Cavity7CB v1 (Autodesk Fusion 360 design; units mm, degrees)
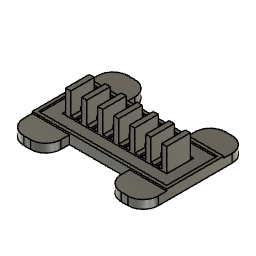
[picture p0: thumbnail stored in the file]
sketch "Sketch1" plane through (0, 0, 0) normal (0, 0, 1) x axis (1, 0, 0)
  line L1 (3, 0) -> (0, 0)
  line L2 (3, 14) -> (3, 0)
  line L3 (0, 14) -> (3, 14)
  line L4 (0, 0) -> (0, 14)
  line L5 (9.5, 14) -> (3, 14)
  line L6 (9.5, 0) -> (9.5, 14)
  line L7 (3, 0) -> (9.5, 0)
  line L8 (9.5, 8) -> (3, 8)
  line L9 (9.5, 6) -> (3, 6)
  line L10 (7, 5.5) -> (5.5, 5.5)
  line L11 (7, 0.7) -> (7, 5.5)
  line L12 (5.5, 0.7) -> (7, 0.7)
  line L13 (5.5, 5.5) -> (5.5, 0.7)
  line L14 (12.5, 0) -> (9.5, 0)
  line L15 (12.5, 14) -> (12.5, 0)
  line L16 (9.5, 14) -> (12.5, 14)
  line L17 (9.5, 0) -> (9.5, 14)
  line L18 (19, 14) -> (12.5, 14)
  line L19 (19, 0) -> (19, 14)
  line L20 (12.5, 0) -> (19, 0)
  line L21 (19, 8) -> (12.5, 8)
  line L22 (19, 6) -> (12.5, 6)
  line L23 (19, 6) -> (19, 8)
  line L24 (12.5, 6) -> (12.5, 8)
  line L25 (16.5, 5.5) -> (15, 5.5)
  line L26 (16.5, 0.7) -> (16.5, 5.5)
  line L27 (15, 0.7) -> (16.5, 0.7)
  line L28 (15, 5.5) -> (15, 0.7)
  line L29 (22, 14) -> (19, 14)
  line L30 (22, 0) -> (22, 14)
  line L31 (19, 0) -> (22, 0)
  line L32 (19, 14) -> (19, 0)
  line L33 (28.5, 14) -> (22, 14)
  line L34 (28.5, 0) -> (28.5, 14)
  line L35 (22, 0) -> (28.5, 0)
  line L36 (22, 14) -> (22, 0)
  line L37 (28.5, 8) -> (22, 8)
  line L38 (28.5, 6) -> (28.5, 8)
  line L39 (22, 6) -> (28.5, 6)
  line L40 (22, 8) -> (22, 6)
  line L41 (26, 5.5) -> (24.5, 5.5)
  line L42 (26, 0.7) -> (26, 5.5)
  line L43 (24.5, 0.7) -> (26, 0.7)
  line L44 (24.5, 5.5) -> (24.5, 0.7)
  line L45 (31.5, 14) -> (28.5, 14)
  line L46 (31.5, 0) -> (31.5, 14)
  line L47 (28.5, 0) -> (31.5, 0)
  line L48 (28.5, 14) -> (28.5, 0)
  line L49 (38, 14) -> (31.5, 14)
  line L50 (38, 0) -> (38, 14)
  line L51 (31.5, 0) -> (38, 0)
  line L52 (31.5, 14) -> (31.5, 0)
  line L53 (41, 14) -> (38, 14)
  line L54 (41, 0) -> (41, 14)
  line L55 (38, 0) -> (41, 0)
  line L56 (38, 14) -> (38, 0)
  line L57 (47.5, 14) -> (41, 14)
  line L58 (47.5, 0) -> (47.5, 14)
  line L59 (41, 0) -> (47.5, 0)
  line L60 (41, 14) -> (41, 0)
  line L61 (50.5, 14) -> (47.5, 14)
  line L62 (50.5, 0) -> (50.5, 14)
  line L63 (47.5, 0) -> (50.5, 0)
  line L64 (47.5, 14) -> (47.5, 0)
  line L65 (57, 14) -> (50.5, 14)
  line L66 (57, 0) -> (57, 14)
  line L67 (50.5, 0) -> (57, 0)
  line L68 (50.5, 14) -> (50.5, 0)
  line L69 (60, 14) -> (57, 14)
  line L70 (60, 0) -> (60, 14)
  line L71 (57, 0) -> (60, 0)
  line L72 (57, 14) -> (57, 0)
  line L73 (38, 8) -> (31.5, 8)
  line L74 (38, 6) -> (38, 8)
  line L75 (31.5, 6) -> (38, 6)
  line L76 (31.5, 8) -> (31.5, 6)
  line L77 (47.5, 8) -> (41, 8)
  line L78 (47.5, 6) -> (47.5, 8)
  line L79 (41, 6) -> (47.5, 6)
  line L80 (41, 8) -> (41, 6)
  line L81 (57, 8) -> (50.5, 8)
  line L82 (57, 6) -> (57, 8)
  line L83 (50.5, 6) -> (57, 6)
  line L84 (50.5, 8) -> (50.5, 6)
  line L85 (35.5, 5.5) -> (34, 5.5)
  line L86 (35.5, 0.7) -> (35.5, 5.5)
  line L87 (34, 0.7) -> (35.5, 0.7)
  line L88 (34, 5.5) -> (34, 0.7)
  line L89 (45, 5.5) -> (43.5, 5.5)
  line L90 (45, 0.7) -> (45, 5.5)
  line L91 (43.5, 0.7) -> (45, 0.7)
  line L92 (43.5, 5.5) -> (43.5, 0.7)
  line L93 (54.5, 5.5) -> (53, 5.5)
  line L94 (54.5, 0.7) -> (54.5, 5.5)
  line L95 (53, 0.7) -> (54.5, 0.7)
  line L96 (53, 5.5) -> (53, 0.7)
  line L97 (62, 7) -> (-6, 7)
  line L98 (54.5, 8.5) -> (53, 8.5)
  line L99 (53, 8.5) -> (53, 13.3)
  line L100 (53, 13.3) -> (54.5, 13.3)
  line L101 (54.5, 13.3) -> (54.5, 8.5)
  line L102 (43.5, 13.3) -> (45, 13.3)
  line L103 (45, 13.3) -> (45, 8.5)
  line L104 (45, 8.5) -> (43.5, 8.5)
  line L105 (43.5, 8.5) -> (43.5, 13.3)
  line L106 (35.5, 8.5) -> (34, 8.5)
  line L107 (34, 8.5) -> (34, 13.3)
  line L108 (34, 13.3) -> (35.5, 13.3)
  line L109 (35.5, 13.3) -> (35.5, 8.5)
  line L110 (24.5, 13.3) -> (26, 13.3)
  line L111 (24.5, 8.5) -> (24.5, 13.3)
  line L112 (26, 8.5) -> (24.5, 8.5)
  line L113 (26, 13.3) -> (26, 8.5)
  line L114 (16.5, 13.3) -> (16.5, 8.5)
  line L115 (15, 13.3) -> (16.5, 13.3)
  line L116 (15, 8.5) -> (15, 13.3)
  line L117 (16.5, 8.5) -> (15, 8.5)
  line L118 (7, 13.3) -> (7, 8.5)
  line L119 (5.5, 13.3) -> (7, 13.3)
  line L120 (5.5, 8.5) -> (5.5, 13.3)
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  point P1 (0, 0)
  point P2 (0, 0)
  point P8 (3, 8)
  point P9 (9.5, 8)
  point P10 (3, 6)
  point P11 (9.5, 6)
  point P21 (12.5, 8)
  point P22 (19, 8)
  point P23 (12.5, 6)
  point P24 (19, 6)
  point P35 (22, 8)
  point P64 (31.5, 8)
  point P68 (41, 8)
  point P72 (50.5, 8)
  point P12 (5.5, 5.5)
  point P113 (5.5, 8.5)
  point P13 (7, 5.5)
  point P110 (7, 8.5)
  point P14 (7, 0.7)
  point P111 (7, 13.3)
  point P15 (5.5, 0.7)
  point P112 (5.5, 13.3)
  point P25 (15, 5.5)
  point P109 (15, 8.5)
  point P26 (16.5, 5.5)
  point P106 (16.5, 8.5)
  point P27 (16.5, 0.7)
  point P107 (16.5, 13.3)
  point P28 (15, 0.7)
  point P108 (15, 13.3)
  point P39 (24.5, 5.5)
  point P104 (24.5, 8.5)
  point P40 (26, 5.5)
  point P105 (26, 8.5)
  point P41 (26, 0.7)
  point P102 (26, 13.3)
  point P42 (24.5, 0.7)
  point P103 (24.5, 13.3)
  point P76 (34, 5.5)
  point P98 (34, 8.5)
  point P77 (35.5, 5.5)
  point P99 (35.5, 8.5)
  point P78 (35.5, 0.7)
  point P101 (35.5, 13.3)
  point P79 (34, 0.7)
  point P100 (34, 13.3)
  point P80 (43.5, 5.5)
  point P97 (43.5, 8.5)
  point P81 (45, 5.5)
  point P96 (45, 8.5)
  point P82 (45, 0.7)
  point P94 (45, 13.3)
  point P83 (43.5, 0.7)
  point P95 (43.5, 13.3)
  point P84 (53, 5.5)
  point P90 (53, 8.5)
  point P85 (54.5, 5.5)
  point P91 (54.5, 8.5)
  point P86 (54.5, 0.7)
  point P93 (54.5, 13.3)
  point P87 (53, 0.7)
  point P92 (53, 13.3)
  point P114 (0, 0)
  point P3 (3, 0)
  point P5 (0, 14)
  point P4 (3, 14)
  point P6 (9.5, 14)
  point P7 (9.5, 0)
  point P16 (12.5, 0)
  point P18 (9.5, 14)
  point P17 (12.5, 14)
  point P19 (19, 14)
  point P29 (22, 14)
  point P31 (19, 0)
  point P32 (28.5, 14)
  point P34 (22, 0)
  point P36 (28.5, 8)
  point P38 (22, 6)
  point P43 (31.5, 14)
  point P45 (28.5, 0)
  point P46 (38, 14)
  point P48 (31.5, 0)
  point P49 (41, 14)
  point P51 (38, 0)
  point P52 (47.5, 14)
  point P54 (41, 0)
  point P55 (50.5, 14)
  point P57 (47.5, 0)
  point P58 (57, 14)
  point P60 (50.5, 0)
  point P61 (60, 14)
  point P63 (57, 0)
  point P65 (38, 8)
  point P67 (31.5, 6)
  point P69 (47.5, 8)
  point P71 (41, 6)
  point P73 (57, 8)
  point P75 (50.5, 6)
  horizontal L1
  vertical L2
  horizontal L3
  vertical L4
  coincident P1 P2
  perpendicular L2 L5
  perpendicular L5 L6
  coincident L2 P8
  coincident L6 P9
  perpendicular L6 L8
  coincident L2 P10
  coincident L6 P11
  perpendicular L6 L9
  horizontal L10
  vertical L11
  horizontal L12
  vertical L13
  horizontal L14
  vertical L15
  horizontal L16
  vertical L17
  perpendicular L15 L18
  perpendicular L18 L19
  perpendicular L15 L20
  coincident L15 P21
  coincident L19 P22
  perpendicular L19 L21
  coincident L15 P23
  coincident L19 P24
  perpendicular L19 L22
  horizontal L25
  vertical L26
  horizontal L27
  vertical L28
  horizontal L29
  vertical L30
  horizontal L31
  vertical L32
  horizontal L33
  vertical L34
  horizontal L35
  vertical L36
  horizontal L37
  vertical L38
  horizontal L39
  vertical L40
  coincident L30 P35
  horizontal L41
  vertical L42
  horizontal L43
  vertical L44
  horizontal L45
  vertical L46
  horizontal L47
  vertical L48
  horizontal L49
  vertical L50
  horizontal L51
  vertical L52
  horizontal L53
  vertical L54
  horizontal L55
  vertical L56
  horizontal L57
  vertical L58
  horizontal L59
  vertical L60
  horizontal L61
  vertical L62
  horizontal L63
  vertical L64
  horizontal L65
  vertical L66
  horizontal L67
  vertical L68
  horizontal L69
  vertical L70
  horizontal L71
  vertical L72
  horizontal L73
  vertical L74
  horizontal L75
  vertical L76
  coincident L46 P64
  horizontal L77
  vertical L78
  horizontal L79
  vertical L80
  coincident L60 P68
  horizontal L81
  vertical L82
  horizontal L83
  vertical L84
  coincident L68 P72
  horizontal L85
  vertical L86
  horizontal L87
  vertical L88
  horizontal L89
  vertical L90
  horizontal L91
  vertical L92
  horizontal L93
  vertical L94
  horizontal L95
  vertical L96
  perpendicular L70 L97
  symmetric P12 L97 P113
  symmetric P13 L97 P110
  symmetric P14 L97 P111
  symmetric P15 L97 P112
  symmetric P25 L97 P109
  symmetric P26 L97 P106
  symmetric P27 L97 P107
  symmetric P28 L97 P108
  symmetric P39 L97 P104
  symmetric P40 L97 P105
  symmetric P41 L97 P102
  symmetric P42 L97 P103
  symmetric P76 L97 P98
  symmetric P77 L97 P99
  symmetric P78 L97 P101
  symmetric P79 L97 P100
  symmetric P80 L97 P97
  symmetric P81 L97 P96
  symmetric P82 L97 P94
  symmetric P83 L97 P95
  symmetric P84 L97 P90
  symmetric P85 L97 P91
  symmetric P86 L97 P93
  symmetric P87 L97 P92
  coincident P1 P114
  dimension "d1" distance P2 P3 = 3
  dimension "d2" distance P2 P5 = 14
  dimension "d3" distance P4 P6 = 6.5
  dimension "d4" distance P6 P7 = 14
  dimension "d5" distance L5 L8 = 6
  dimension "d6" distance L8 L9 = 2
  dimension "d7" distance L6 L11 = 2.5
  dimension "d8" distance L2 L13 = 2.5
  dimension "d9" distance L7 L12 = 0.7
  dimension "d10" distance L9 L10 = 0.5
  dimension "d11" distance P7 P16 = 3
  dimension "d12" distance P7 P18 = 14
  dimension "d13" distance P17 P19 = 6.5
  dimension "d14" distance L22 L25 = 0.5
  dimension "d15" distance L20 L27 = 0.7
  dimension "d16" distance L15 L28 = 2.5
  dimension "d17" distance L19 L26 = 2.5
  dimension "d18" distance P19 P29 = 3
  dimension "d19" distance P19 P31 = 14
  dimension "d20" distance P29 P32 = 6.5
  dimension "d21" distance P29 P34 = 14
  dimension "d22" distance P35 P36 = 6.5
  dimension "d23" distance P35 P38 = 2
  dimension "d24" distance L33 L37 = 6
  dimension "d25" distance P32 P43 = 3
  dimension "d26" distance P32 P45 = 14
  dimension "d27" distance P43 P46 = 6.5
  dimension "d28" distance P43 P48 = 14
  dimension "d29" distance P46 P49 = 3
  dimension "d30" distance P46 P51 = 14
  dimension "d31" distance P49 P52 = 6.5
  dimension "d32" distance P49 P54 = 14
  dimension "d33" distance P52 P55 = 3
  dimension "d34" distance P52 P57 = 14
  dimension "d35" distance P55 P58 = 6.5
  dimension "d36" distance P55 P60 = 14
  dimension "d37" distance P58 P61 = 3
  dimension "d38" distance P58 P63 = 14
  dimension "d39" distance P64 P65 = 6.5
  dimension "d40" distance P64 P67 = 2
  dimension "d41" distance P68 P69 = 6.5
  dimension "d42" distance P68 P71 = 2
  dimension "d43" distance P72 P73 = 6.5
  dimension "d44" distance P72 P75 = 2
  dimension "d45" distance L65 L81 = 6
  dimension "d46" distance L57 L77 = 6
  dimension "d47" distance L49 L73 = 6
  dimension "d48" distance L39 L41 = 0.5
  dimension "d49" distance L35 L43 = 0.7
  dimension "d50" distance L42 L48 = 2.5
  dimension "d51" distance L30 L44 = 2.5
  dimension "d52" distance L83 L93 = 0.5
  dimension "d53" distance L67 L95 = 0.7
  dimension "d54" distance L66 L94 = 2.5
  dimension "d55" distance L62 L96 = 2.5
  dimension "d56" distance L64 L90 = 2.5
  dimension "d57" distance L54 L92 = 2.5
  dimension "d58" distance L59 L91 = 0.7
  dimension "d59" distance L79 L89 = 0.5
  dimension "d60" distance L75 L85 = 0.5
  dimension "d61" distance L51 L87 = 0.7
  dimension "d62" distance L50 L86 = 2.5
  dimension "d63" distance L46 L88 = 2.5
  dimension "d64" distance L18 L21 = 6
  dimension "d65" distance L20 L22 = 6
  dimension "d66" distance L69 L97 = 7
  dimension "d67" = 1
  dimension "d68" = 8
  dimension "d69" = 9.9
extrude "Extrude1" new body sketch "Sketch1" against normal blind 5
extrude "Extrude2" cut sketch "Sketch1" against normal blind 1
extrude "Extrude3" add sketch "Sketch1" along normal blind 13 and against normal blind 1
extrude "Extrude4" add sketch "Sketch1" profile of L2 L6 L8 L9 L15 L17 L19 L21 L22 L23 L24 L30 L32 L34 L36 L37 L38 L39 L40 L46 L48 L50 L52 L54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 along normal blind 2
extrude "Extrude5" add sketch "Sketch1" along normal blind 1
sketch "Sketch2" plane through (0, -9.9, 0) normal (0, -1, 0) x axis (1, 0, 0)
  line L1 (-9.9, -5) -> (-9.9, 1)
  line L2 (69.9, -5) -> (-9.9, -5)
  line L3 (69.9, 1) -> (69.9, -5)
  line L4 (-9.9, 1) -> (69.9, 1)
  line L5 (12.1, -5) -> (-9.9, -5)
  line L6 (12.1, 0) -> (12.1, -5)
  line L7 (-9.9, 0) -> (12.1, 0)
  line L8 (-9.9, -5) -> (-9.9, 0)
  line L9 (47.9, -5) -> (69.9, -5)
  line L10 (47.9, 0) -> (47.9, -5)
  line L11 (69.9, 0) -> (47.9, 0)
  line L12 (69.9, -5) -> (69.9, 0)
  point P3 (-9.9, -5)
  point P6 (-9.9, -5)
  point P4 (69.9, -5)
  point P10 (69.9, -5)
  point P7 (12.1, -5)
  point P9 (-9.9, 0)
  point P11 (47.9, -5)
  point P13 (69.9, 0)
  horizontal L5
  vertical L6
  horizontal L7
  vertical L8
  coincident P3 P6
  horizontal L9
  vertical L10
  horizontal L11
  vertical L12
  coincident P4 P10
  dimension "d82" distance P6 P7 = 22
  dimension "d83" distance P6 P9 = 5
  dimension "d84" distance P10 P11 = 22
  dimension "d85" distance P10 P13 = 5
extrude "Extrude6" add sketch "Sketch2" profile of L1 L2 L3 L5 L6 L7 L8 L9 L10 L11 L12 along normal blind 14
sketch "Sketch3" plane through (0, 23.9, 0) normal (0, 1, 0) x axis (-1, 0, 0)
  line L1 (-69.9, -5) -> (-69.9, 1)
  line L2 (9.9, -5) -> (-69.9, -5)
  line L3 (9.9, 1) -> (9.9, -5)
  line L4 (-69.9, 1) -> (9.9, 1)
  line L5 (-47.9, -5) -> (-69.9, -5)
  line L6 (-47.9, 0) -> (-47.9, -5)
  line L7 (-69.9, 0) -> (-47.9, 0)
  line L8 (-69.9, -5) -> (-69.9, 0)
  line L9 (-12.1, -5) -> (9.9, -5)
  line L10 (-12.1, 0) -> (-12.1, -5)
  line L11 (9.9, 0) -> (-12.1, 0)
  line L12 (9.9, -5) -> (9.9, 0)
  point P3 (-69.9, -5)
  point P6 (-69.9, -5)
  point P4 (9.9, -5)
  point P10 (9.9, -5)
  point P7 (-47.9, -5)
  point P9 (-69.9, 0)
  point P11 (-12.1, -5)
  point P13 (9.9, 0)
  horizontal L5
  vertical L6
  horizontal L7
  vertical L8
  coincident P3 P6
  horizontal L9
  vertical L10
  horizontal L11
  vertical L12
  coincident P4 P10
  dimension "d88" distance P6 P7 = 22
  dimension "d89" distance P6 P9 = 5
  dimension "d90" distance P10 P11 = 22
  dimension "d91" distance P10 P13 = 5
extrude "Extrude7" add sketch "Sketch3" profile of L1 L2 L3 L5 L6 L7 L8 L9 L10 L11 L12 along normal blind 14
fillet "Fillet1" radius 9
